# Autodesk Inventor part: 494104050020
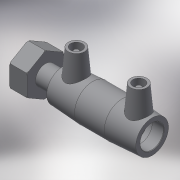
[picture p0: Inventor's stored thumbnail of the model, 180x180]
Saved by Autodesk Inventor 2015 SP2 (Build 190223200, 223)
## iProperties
Created: 2017-06
Part Number: 494104050020
Material: Generic
Description: PLASSON FEMALE FREE NUT TRANSITION COUPLER 50-2"
Document SubType Name: Modeling
Designer: KIM
Mass: 55.0731 g
Surface Area: 148.067 cm^2
Volume: 55.0731 cm^3
Density: 1 g/cm^3
Appearance: Default
Author: KIM
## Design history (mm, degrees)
derived "494104.ipt"
feature "Solid1::494104.ipt"
tag "TaggingFeature1"
body "Solid1"
other parameters: "d2" = 67, "d3" = 49, "d4" = 33.33333, "d5" = 60.3, "d6" = 47.5, "d8" = 168 deg, "d10" = 19.6, "d11" = 6.53333, "d29" = 52, "d30" = 14, "d31" = 35, "d34" = 5 deg, "d41" = 4, "d42" = 14, "d43" = 0, "d48" = 3, "d49" = 0, "d55" = 41, "d57" = 38, "d80" = 1, "d83" = 22.77778, "d84" = 15.03333, "d85" = 1.50333, "d86" = 45.3248, "d87" = 56.656, "d88" = 84.984, "d89" = 67, "d90" = 1.69968, "d94" = 0, "d95" = 1.50333, "d96" = 39.6592, "L_" = 141, "L_1" = 49, "D_1" = 67, "A_" = 52, "d_2" = 12, "L_2" = 41, "D_" = 38, "G_" = 56.656
